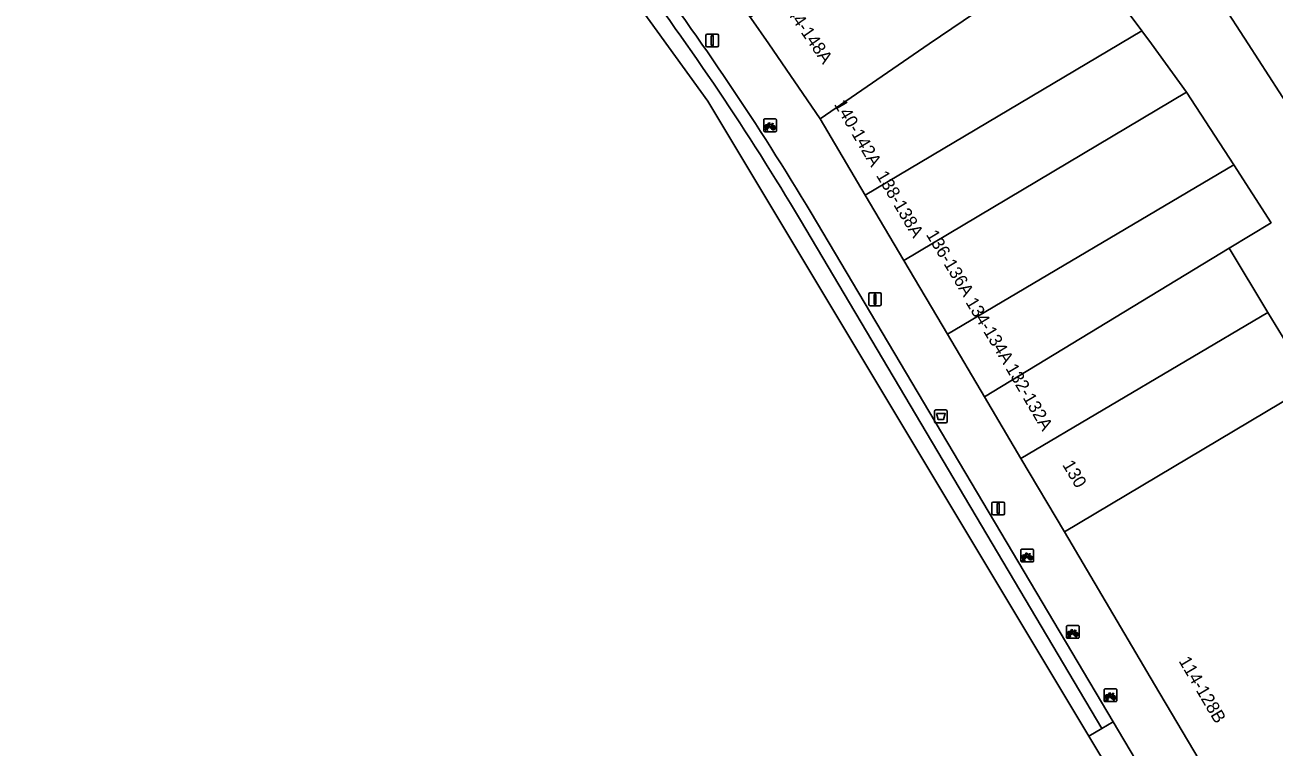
# Model space of a CAD drawing. Extents: x 160856 to 161310, y 384024 to 384878.
# Drawn here: x 160978.4 to 161076.4, y 384444.8 to 384501.5 of the extents above; entities that cross this region are included whole.
import ezdxf

# ---------------------------------------------------------------- set-up
doc = ezdxf.new("R2010")
doc.units = 0
for name, color, linetype in [('IMGEO_Afvalbak', 7, 'Continuous'), ('IMGEO_Fietsenrek', 7, 'Continuous'), ('IMGEO_Fietspad_gesloten', 7, 'Continuous'), ('IMGEO_Fietspad_open', 7, 'Continuous'), ('IMGEO_Lichtmast', 7, 'Continuous'), ('IMGEO_Pand', 7, 'Continuous'), ('IMGEO_Pand_nummerreeks', 7, 'Continuous'), ('IMGEO_Rijbaan_lokaal_open', 7, 'Continuous'), ('IMGEO_Voetpad_open', 7, 'Continuous')]:
    doc.layers.add(name, color=color, linetype=linetype)

msp = doc.modelspace()

# ---------------------------------------------------------------- linework, layer by layer
at = {"layer": 'IMGEO_Afvalbak'}
for p, q in [((161049.779, 384470.364), (161049.779, 384471.164)), ((161049.779, 384471.164), (161049.779, 384470.364)), ((161049.879, 384471.264), (161050.669, 384471.264)), ((161050.669, 384471.264), (161049.879, 384471.264)), ((161050.769, 384471.164), (161050.769, 384470.364)), ((161050.769, 384470.364), (161050.769, 384471.164)), ((161050.669, 384470.264), (161049.879, 384470.264)), ((161049.879, 384470.264), (161050.669, 384470.264))]:
    msp.add_line(p, q, dxfattribs=at)
msp.add_lwpolyline([(161049.922, 384470.978), (161050.626, 384470.978), (161050.477, 384470.508), (161050.071, 384470.508), (161049.922, 384470.978)], dxfattribs=at)
for centre, start, end in [((161049.879, 384471.164), 90, 180), ((161049.879, 384471.164), 90, 180), ((161050.669, 384471.164), 0, 90), ((161050.669, 384471.164), 360, 90), ((161049.879, 384470.364), 180, 270), ((161049.879, 384470.364), 180, 270), ((161050.669, 384470.364), 270, 0), ((161050.669, 384470.364), 270, 0)]:
    msp.add_arc(centre, 0.1, start, end, dxfattribs=at)
at = {"layer": 'IMGEO_Fietsenrek'}
for p, q in [((161036.368, 384493.185), (161036.368, 384494.026)), ((161036.368, 384494.026), (161036.368, 384493.185)), ((161036.443, 384494.11), (161037.284, 384494.11)), ((161037.284, 384494.11), (161036.443, 384494.11)), ((161037.055, 384493.659), (161037.091, 384493.564)), ((161037.368, 384494.035), (161037.368, 384493.194)), ((161037.368, 384493.194), (161037.368, 384494.035)), ((161037.293, 384493.11), (161036.452, 384493.11)), ((161036.452, 384493.11), (161037.293, 384493.11)), ((161036.495, 384493.194), (161036.534, 384493.354)), ((161036.529, 384493.194), (161036.495, 384493.194)), ((161036.564, 384493.342), (161036.529, 384493.194)), ((161036.606, 384493.366), (161036.605, 384493.37)), ((161036.647, 384493.194), (161036.613, 384493.336)), ((161036.637, 384493.377), (161036.638, 384493.37)), ((161036.645, 384493.34), (161036.68, 384493.194)), ((161036.68, 384493.194), (161036.647, 384493.194)), ((161056.556, 384459.416), (161056.556, 384460.257)), ((161056.556, 384460.257), (161056.556, 384459.416)), ((161056.631, 384460.341), (161057.472, 384460.341)), ((161057.472, 384460.341), (161056.631, 384460.341)), ((161057.556, 384460.266), (161057.556, 384459.425)), ((161057.556, 384459.425), (161057.556, 384460.266)), ((161057.481, 384459.341), (161056.64, 384459.341)), ((161056.64, 384459.341), (161057.481, 384459.341)), ((161056.683, 384459.425), (161056.722, 384459.585)), ((161056.717, 384459.425), (161056.683, 384459.425)), ((161056.752, 384459.573), (161056.717, 384459.425)), ((161056.794, 384459.597), (161056.793, 384459.601)), ((161056.835, 384459.425), (161056.801, 384459.567)), ((161056.825, 384459.608), (161056.826, 384459.601)), ((161056.833, 384459.571), (161056.868, 384459.425)), ((161056.868, 384459.425), (161056.835, 384459.425)), ((161057.243, 384459.89), (161057.279, 384459.795)), ((161060.212, 384454.337), (161061.053, 384454.337)), ((161061.053, 384454.337), (161060.212, 384454.337)), ((161060.137, 384453.412), (161060.137, 384454.253)), ((161060.137, 384454.253), (161060.137, 384453.412)), ((161060.264, 384453.421), (161060.303, 384453.581)), ((161060.298, 384453.421), (161060.264, 384453.421)), ((161060.333, 384453.569), (161060.298, 384453.421)), ((161060.375, 384453.593), (161060.374, 384453.597)), ((161060.416, 384453.421), (161060.382, 384453.563)), ((161060.406, 384453.604), (161060.407, 384453.597)), ((161060.414, 384453.567), (161060.449, 384453.421)), ((161060.449, 384453.421), (161060.416, 384453.421)), ((161060.824, 384453.886), (161060.86, 384453.791)), ((161061.137, 384454.262), (161061.137, 384453.421)), ((161061.137, 384453.421), (161061.137, 384454.262)), ((161061.062, 384453.337), (161060.221, 384453.337)), ((161060.221, 384453.337), (161061.062, 384453.337)), ((161063.094, 384448.442), (161063.094, 384449.283)), ((161063.094, 384449.283), (161063.094, 384448.442)), ((161063.169, 384449.367), (161064.01, 384449.367)), ((161064.01, 384449.367), (161063.169, 384449.367)), ((161063.221, 384448.451), (161063.26, 384448.611)), ((161063.255, 384448.451), (161063.221, 384448.451)), ((161063.29, 384448.599), (161063.255, 384448.451)), ((161063.332, 384448.623), (161063.331, 384448.627)), ((161063.373, 384448.451), (161063.339, 384448.593)), ((161063.363, 384448.634), (161063.364, 384448.627)), ((161063.371, 384448.597), (161063.406, 384448.451)), ((161063.406, 384448.451), (161063.373, 384448.451)), ((161063.781, 384448.916), (161063.817, 384448.821)), ((161064.094, 384449.292), (161064.094, 384448.451)), ((161064.094, 384448.451), (161064.094, 384449.292)), ((161064.019, 384448.367), (161063.178, 384448.367)), ((161063.178, 384448.367), (161064.019, 384448.367))]:
    msp.add_line(p, q, dxfattribs=at)
for points in [[(161036.702, 384493.584), (161036.65, 384493.494), (161036.61, 384493.469), (161036.611, 384493.516), (161036.666, 384493.61)], [(161036.681, 384493.636), (161036.776, 384493.8), (161036.862, 384493.786), (161036.864, 384493.777), (161036.808, 384493.766), (161036.781, 384493.721), (161037.037, 384493.68)], [(161036.977, 384493.392), (161036.927, 384493.392), (161036.736, 384493.643), (161036.717, 384493.611)], [(161037.024, 384493.655), (161036.767, 384493.696), (161036.75, 384493.667), (161036.917, 384493.447), (161037.024, 384493.655)], [(161037.072, 384493.557), (161037.042, 384493.634), (161036.933, 384493.416), (161036.976, 384493.416)], [(161037.037, 384493.68), (161037.062, 384493.729), (161037.056, 384493.733), (161037.033, 384493.737), (161037.021, 384493.744), (161037.02, 384493.747), (161037.022, 384493.752), (161037.117, 384493.737), (161037.119, 384493.727), (161037.109, 384493.714), (161037.097, 384493.708), (161037.083, 384493.714), (161037.055, 384493.659)], [(161037.006, 384493.416), (161037.126, 384493.415), (161037.082, 384493.529)], [(161037.102, 384493.536), (161037.157, 384493.391), (161037.007, 384493.391)], [(161056.89, 384459.815), (161056.838, 384459.725), (161056.798, 384459.7), (161056.799, 384459.747), (161056.854, 384459.841)], [(161056.869, 384459.867), (161056.964, 384460.031), (161057.05, 384460.017), (161057.052, 384460.008), (161056.996, 384459.997), (161056.969, 384459.952), (161057.225, 384459.911)], [(161057.165, 384459.623), (161057.115, 384459.623), (161056.924, 384459.874), (161056.905, 384459.842)], [(161057.212, 384459.886), (161056.955, 384459.927), (161056.938, 384459.898), (161057.105, 384459.678), (161057.212, 384459.886)], [(161057.26, 384459.788), (161057.23, 384459.865), (161057.121, 384459.647), (161057.164, 384459.647)], [(161057.194, 384459.647), (161057.314, 384459.646), (161057.27, 384459.76)], [(161057.29, 384459.767), (161057.345, 384459.622), (161057.195, 384459.622)], [(161057.225, 384459.911), (161057.25, 384459.96), (161057.244, 384459.964), (161057.221, 384459.968), (161057.209, 384459.975), (161057.208, 384459.978), (161057.21, 384459.983), (161057.305, 384459.968), (161057.307, 384459.958), (161057.297, 384459.945), (161057.285, 384459.939), (161057.271, 384459.945), (161057.243, 384459.89)], [(161060.471, 384453.811), (161060.419, 384453.721), (161060.379, 384453.696), (161060.38, 384453.743), (161060.435, 384453.837)], [(161060.45, 384453.863), (161060.545, 384454.027), (161060.631, 384454.013), (161060.633, 384454.004), (161060.577, 384453.993), (161060.55, 384453.948), (161060.806, 384453.907)], [(161060.746, 384453.619), (161060.696, 384453.619), (161060.505, 384453.87), (161060.486, 384453.838)], [(161060.793, 384453.882), (161060.536, 384453.923), (161060.519, 384453.894), (161060.686, 384453.674), (161060.793, 384453.882)], [(161060.841, 384453.784), (161060.811, 384453.861), (161060.702, 384453.643), (161060.745, 384453.643)], [(161060.775, 384453.643), (161060.895, 384453.642), (161060.851, 384453.756)], [(161060.871, 384453.763), (161060.926, 384453.618), (161060.776, 384453.618)], [(161060.806, 384453.907), (161060.831, 384453.956), (161060.825, 384453.96), (161060.802, 384453.964), (161060.79, 384453.971), (161060.789, 384453.974), (161060.791, 384453.979), (161060.886, 384453.964), (161060.888, 384453.954), (161060.878, 384453.941), (161060.866, 384453.935), (161060.852, 384453.941), (161060.824, 384453.886)], [(161063.428, 384448.841), (161063.376, 384448.751), (161063.336, 384448.726), (161063.337, 384448.773), (161063.392, 384448.867)], [(161063.407, 384448.893), (161063.502, 384449.057), (161063.588, 384449.043), (161063.59, 384449.034), (161063.534, 384449.023), (161063.507, 384448.978), (161063.763, 384448.937)], [(161063.703, 384448.649), (161063.653, 384448.649), (161063.462, 384448.9), (161063.443, 384448.868)], [(161063.75, 384448.912), (161063.493, 384448.953), (161063.476, 384448.924), (161063.643, 384448.704), (161063.75, 384448.912)], [(161063.798, 384448.814), (161063.768, 384448.891), (161063.659, 384448.673), (161063.702, 384448.673)], [(161063.732, 384448.673), (161063.852, 384448.672), (161063.808, 384448.786)], [(161063.828, 384448.793), (161063.883, 384448.648), (161063.733, 384448.648)], [(161063.763, 384448.937), (161063.788, 384448.986), (161063.782, 384448.99), (161063.759, 384448.994), (161063.747, 384449.001), (161063.746, 384449.004), (161063.748, 384449.009), (161063.843, 384448.994), (161063.845, 384448.984), (161063.835, 384448.971), (161063.823, 384448.965), (161063.809, 384448.971), (161063.781, 384448.916)]]:
    msp.add_lwpolyline(points, dxfattribs=at)
for centre, radius, start, end in [((161036.446, 384494.032), 0.0779, 92.4484, 184.28452), ((161036.446, 384494.032), 0.0779, 92.4484, 184.28452), ((161036.608, 384493.495), 0.159, 62.67661, 242.13685), ((161036.608, 384493.495), 0.129, 63.31916, 238.90302), ((161036.608, 384493.495), 0.129, 283.60429, 43.43025), ((161036.608, 384493.495), 0.159, 283.5766, 46.60424), ((161037.135, 384493.411), 0.159, 113.3408, 178.32165), ((161037.135, 384493.411), 0.159, 187.0065, 105.77075), ((161037.29, 384494.032), 0.0779, 2.4484, 94.28452), ((161037.29, 384494.032), 0.0779, 2.4484, 94.28452), ((161036.446, 384493.188), 0.0779, 182.4484, 274.28452), ((161036.446, 384493.188), 0.0779, 182.4484, 274.28452), ((161036.588, 384493.366), 0.0499, 12.8025, 158.69338), ((161036.608, 384493.495), 0.159, 253.99666, 271.78671), ((161036.588, 384493.366), 0.0174, 12.8025, 163.45023), ((161036.608, 384493.495), 0.129, 253.41502, 269.02044), ((161037.135, 384493.411), 0.129, 113.92302, 177.95563), ((161037.135, 384493.411), 0.129, 188.67146, 104.58832), ((161037.29, 384493.188), 0.0779, 272.4484, 4.28452), ((161037.29, 384493.188), 0.0779, 272.4484, 4.28452), ((161056.634, 384460.263), 0.0779, 92.4484, 184.28452), ((161056.634, 384460.263), 0.0779, 92.4484, 184.28452), ((161057.478, 384460.263), 0.0779, 2.4484, 94.28452), ((161057.478, 384460.263), 0.0779, 2.4484, 94.28452), ((161056.634, 384459.419), 0.0779, 182.4484, 274.28452), ((161056.634, 384459.419), 0.0779, 182.4484, 274.28452), ((161056.796, 384459.726), 0.159, 62.67661, 242.13685), ((161056.796, 384459.726), 0.129, 63.31916, 238.90302), ((161056.776, 384459.597), 0.0499, 12.8025, 158.69338), ((161056.796, 384459.726), 0.159, 253.99666, 271.78671), ((161056.776, 384459.597), 0.0174, 12.8025, 163.45023), ((161056.796, 384459.726), 0.129, 253.41502, 269.02044), ((161056.796, 384459.726), 0.129, 283.60429, 43.43025), ((161056.796, 384459.726), 0.159, 283.5766, 46.60424), ((161057.323, 384459.642), 0.159, 113.3408, 178.32165), ((161057.323, 384459.642), 0.159, 187.0065, 105.77075), ((161057.323, 384459.642), 0.129, 113.92302, 177.95563), ((161057.323, 384459.642), 0.129, 188.67146, 104.58832), ((161057.478, 384459.419), 0.0779, 272.4484, 4.28452), ((161057.478, 384459.419), 0.0779, 272.4484, 4.28452), ((161060.215, 384454.259), 0.0779, 92.4484, 184.28452), ((161060.215, 384454.259), 0.0779, 92.4484, 184.28452), ((161061.059, 384454.259), 0.0779, 2.4484, 94.28452), ((161061.059, 384454.259), 0.0779, 2.4484, 94.28452), ((161060.215, 384453.415), 0.0779, 182.4484, 274.28452), ((161060.215, 384453.415), 0.0779, 182.4484, 274.28452), ((161060.377, 384453.722), 0.159, 62.67661, 242.13685), ((161060.377, 384453.722), 0.129, 63.31916, 238.90302), ((161060.357, 384453.593), 0.0499, 12.8025, 158.69338), ((161060.377, 384453.722), 0.159, 253.99666, 271.78671), ((161060.357, 384453.593), 0.0174, 12.8025, 163.45023), ((161060.377, 384453.722), 0.129, 253.41502, 269.02044), ((161060.377, 384453.722), 0.129, 283.60429, 43.43025), ((161060.377, 384453.722), 0.159, 283.5766, 46.60424), ((161060.904, 384453.638), 0.159, 113.3408, 178.32165), ((161060.904, 384453.638), 0.159, 187.0065, 105.77075), ((161060.904, 384453.638), 0.129, 113.92302, 177.95563), ((161060.904, 384453.638), 0.129, 188.67146, 104.58832), ((161061.059, 384453.415), 0.0779, 272.4484, 4.28452), ((161061.059, 384453.415), 0.0779, 272.4484, 4.28452), ((161063.172, 384449.289), 0.0779, 92.4484, 184.28452), ((161063.172, 384449.289), 0.0779, 92.4484, 184.28452), ((161063.334, 384448.752), 0.159, 62.67661, 242.13685), ((161063.334, 384448.752), 0.129, 63.31916, 238.90302), ((161063.314, 384448.623), 0.0499, 12.8025, 158.69338), ((161063.334, 384448.752), 0.159, 253.99666, 271.78671), ((161063.314, 384448.623), 0.0174, 12.8025, 163.45023), ((161063.334, 384448.752), 0.129, 253.41502, 269.02044), ((161063.334, 384448.752), 0.129, 283.60429, 43.43025), ((161063.334, 384448.752), 0.159, 283.5766, 46.60424), ((161063.861, 384448.668), 0.159, 113.3408, 178.32165), ((161063.861, 384448.668), 0.159, 187.0065, 105.77075), ((161063.861, 384448.668), 0.129, 113.92302, 177.95563), ((161063.861, 384448.668), 0.129, 188.67146, 104.58832), ((161064.016, 384449.289), 0.0779, 2.4484, 94.28452), ((161064.016, 384449.289), 0.0779, 2.4484, 94.28452), ((161064.016, 384448.445), 0.0779, 272.4484, 4.28452), ((161064.016, 384448.445), 0.0779, 272.4484, 4.28452), ((161063.172, 384448.445), 0.0779, 182.4484, 274.28452), ((161063.172, 384448.445), 0.0779, 182.4484, 274.28452)]:
    msp.add_arc(centre, radius, start, end, dxfattribs=at)
at = {"layer": 'IMGEO_Fietspad_gesloten'}
for points in [[(161025.88, 384506.051), (161024.93, 384505.299), (161031.994, 384495.497), (161061.891, 384445.653)], [(161061.891, 384445.653), (161062.919, 384446.259), (161039.255, 384486.177)]]:
    msp.add_lwpolyline(points, dxfattribs=at)
msp.add_arc((160849.822, 384373.128), 220.601, 30.82769, 37.05261, dxfattribs=at)
at = {"layer": 'IMGEO_Fietspad_open'}
msp.add_lwpolyline([(161039.255, 384486.177), (161062.919, 384446.259), (161063.799, 384446.778), (161040.086, 384486.747)], dxfattribs=at)
msp.add_lwpolyline([(161063.662, 384442.699), (161064.671, 384443.305), (161065.547, 384443.832), (161063.799, 384446.778), (161062.919, 384446.259), (161061.891, 384445.653)], close=True, dxfattribs=at)
for centre, radius, start, end in [((160846.585, 384370.955), 225.5, 30.89645, 37.00358), ((160849.822, 384373.128), 220.601, 30.82769, 37.05261)]:
    msp.add_arc(centre, radius, start, end, dxfattribs=at)
at = {"layer": 'IMGEO_Lichtmast'}
for p, q in [((161031.837, 384499.868), (161031.837, 384500.668)), ((161031.837, 384500.668), (161031.837, 384499.868)), ((161031.937, 384500.768), (161032.727, 384500.768)), ((161032.727, 384500.768), (161031.937, 384500.768)), ((161032.827, 384500.668), (161032.827, 384499.868)), ((161032.827, 384499.868), (161032.827, 384500.668)), ((161032.727, 384499.768), (161031.937, 384499.768)), ((161031.937, 384499.768), (161032.727, 384499.768)), ((161044.611, 384479.55), (161044.611, 384480.35)), ((161044.611, 384480.35), (161044.611, 384479.55)), ((161044.711, 384480.45), (161045.501, 384480.45)), ((161045.501, 384480.45), (161044.711, 384480.45)), ((161045.601, 384480.35), (161045.601, 384479.55)), ((161045.601, 384479.55), (161045.601, 384480.35)), ((161045.501, 384479.45), (161044.711, 384479.45)), ((161044.711, 384479.45), (161045.501, 384479.45)), ((161054.287, 384463.135), (161054.287, 384463.935)), ((161054.287, 384463.935), (161054.287, 384463.135)), ((161054.387, 384464.035), (161055.177, 384464.035)), ((161055.177, 384464.035), (161054.387, 384464.035)), ((161055.277, 384463.935), (161055.277, 384463.135)), ((161055.277, 384463.135), (161055.277, 384463.935)), ((161055.177, 384463.035), (161054.387, 384463.035)), ((161054.387, 384463.035), (161055.177, 384463.035))]:
    msp.add_line(p, q, dxfattribs=at)
for points in [[(161032.257, 384500.643), (161032.407, 384500.643), (161032.407, 384499.893), (161032.257, 384499.893), (161032.257, 384500.643)], [(161045.031, 384480.325), (161045.181, 384480.325), (161045.181, 384479.575), (161045.031, 384479.575), (161045.031, 384480.325)], [(161054.707, 384463.91), (161054.857, 384463.91), (161054.857, 384463.16), (161054.707, 384463.16), (161054.707, 384463.91)]]:
    msp.add_lwpolyline(points, dxfattribs=at)
for centre, start, end in [((161031.937, 384500.668), 90, 180), ((161031.937, 384500.668), 90, 180), ((161032.727, 384500.668), 0, 90), ((161032.727, 384500.668), 360, 90), ((161031.937, 384499.868), 180, 270), ((161031.937, 384499.868), 180, 270), ((161032.727, 384499.868), 270, 0), ((161032.727, 384499.868), 270, 0), ((161044.711, 384480.35), 90, 180), ((161044.711, 384480.35), 90, 180), ((161045.501, 384480.35), 0, 90), ((161045.501, 384480.35), 360, 90), ((161044.711, 384479.55), 180, 270), ((161044.711, 384479.55), 180, 270), ((161045.501, 384479.55), 270, 0), ((161045.501, 384479.55), 270, 0), ((161054.387, 384463.935), 90, 180), ((161054.387, 384463.935), 90, 180), ((161055.177, 384463.935), 0, 90), ((161055.177, 384463.935), 360, 90), ((161054.387, 384463.135), 180, 270), ((161054.387, 384463.135), 180, 270), ((161055.177, 384463.135), 270, 0), ((161055.177, 384463.135), 270, 0)]:
    msp.add_arc(centre, 0.1, start, end, dxfattribs=at)
at = {"layer": 'IMGEO_Pand'}
for points in [[(161040.804, 384494.109), (161049.367, 384500), (161060.762, 384507.759), (161060.912, 384507.86), (161055.172, 384515.721), (161035.318, 384502.112), (161035.397, 384501.998), (161036.766, 384500)], [(161086.528, 384500), (161078.403, 384512.582), (161069.859, 384507.042), (161070.066, 384506.722), (161074.406, 384500), (161086.57, 384481.163), (161095.125, 384486.687), (161089.266, 384495.761)], [(161066.061, 384501.015), (161062.467, 384505.869), (161062.285, 384505.641), (161060.762, 384507.759), (161049.367, 384500), (161040.804, 384494.109), (161044.336, 384488.136)], [(161069.571, 384496.22), (161066.804, 384500), (161066.061, 384501.015), (161044.336, 384488.136), (161047.368, 384483.008)], [(161069.571, 384496.22), (161047.368, 384483.008), (161050.789, 384477.224), (161073.262, 384490.514)], [(161072.904, 384483.963), (161076.199, 384485.966), (161073.262, 384490.514), (161050.789, 384477.224), (161053.697, 384472.306)], [(161072.904, 384483.963), (161053.697, 384472.306), (161056.563, 384467.459), (161075.954, 384478.925)], [(161079.386, 384473.255), (161075.954, 384478.925), (161056.563, 384467.459), (161059.97, 384461.697)], [(161079.386, 384473.255), (161059.97, 384461.697), (161067.054, 384449.718), (161074.052, 384437.883), (161077.552, 384431.965), (161085.69, 384435.488), (161085.88, 384434.994), (161095.394, 384438.657), (161094.42, 384441.188), (161097.341, 384442.312), (161094.568, 384450.014), (161094.201, 384451.035), (161087.735, 384461.947), (161080.492, 384474.172)]]:
    msp.add_lwpolyline(points, close=True, dxfattribs=at)
at = {"layer": 'IMGEO_Rijbaan_lokaal_open'}
for points in [[(161086.57, 384481.163), (161074.406, 384500), (161070.066, 384506.722), (161069.859, 384507.042), (161069.287, 384506.671), (161064.523, 384513.188), (161061.847, 384516.849), (161050.778, 384531.991), (161024.428, 384568.037)], [(161021.221, 384561.973), (161025.146, 384556.687), (161029.946, 384550.221), (161029.569, 384549.908), (161034.956, 384543.407), (161038.456, 384538.613), (161041.965, 384533.808), (161045.474, 384529.002), (161048.983, 384524.197), (161055.172, 384515.721), (161060.912, 384507.86), (161060.762, 384507.759), (161062.285, 384505.641), (161062.467, 384505.869), (161066.061, 384501.015), (161066.804, 384500), (161069.571, 384496.22), (161073.262, 384490.514), (161076.199, 384485.966), (161072.904, 384483.963), (161075.954, 384478.925), (161079.386, 384473.255)]]:
    msp.add_lwpolyline(points, dxfattribs=at)
at = {"layer": 'IMGEO_Voetpad_open'}
for points in [[(161036.766, 384500), (161035.397, 384501.998), (161035.318, 384502.112), (161030.638, 384508.94), (161031.821, 384509.921), (161028.032, 384514.494), (161024.243, 384519.066), (161020.454, 384523.638), (161016.665, 384528.211), (161011.287, 384534.701), (161006.157, 384540.892), (161004.916, 384539.863), (161000.723, 384544.923), (161000, 384545.796), (160993.672, 384553.434), (160989.204, 384558.838), (160989.072, 384558.729), (160985.147, 384563.476), (160983.078, 384565.978), (160981.931, 384567.366), (160982.264, 384571.633), (160981.645, 384572.376), (160979.156, 384575.363), (160978.381, 384574.954)], [(161082.898, 384415.232), (161087.871, 384407.534), (161089.488, 384412.11), (161087.978, 384417.265), (161083.529, 384422.548), (161081.445, 384423.321), (161077.145, 384431.612), (161077.552, 384431.965), (161074.052, 384437.883), (161067.054, 384449.718), (161059.97, 384461.697), (161056.563, 384467.459), (161053.697, 384472.306), (161050.789, 384477.224), (161047.368, 384483.008), (161044.336, 384488.136), (161040.804, 384494.109), (161036.766, 384500)], [(161040.086, 384486.747), (161063.799, 384446.778), (161065.547, 384443.832), (161066.518, 384442.195), (161071.087, 384434.493)]]:
    msp.add_lwpolyline(points, dxfattribs=at)
msp.add_arc((160846.585, 384370.955), 225.5, 30.89645, 37.00358, dxfattribs=at)

# ---------------------------------------------------------------- texts
at = {"layer": 'IMGEO_Pand_nummerreeks'}
for s, rotation, p in [('144-148A', 304.73169, (161037.726, 384503.109)), ('140-142A', 300.59574, (161041.869, 384495.256)), ('138-138A', 300.59574, (161045.167, 384489.678)), ('136-136A', 301.10881, (161049.084, 384485.034)), ('134-134A', 301.38319, (161052.186, 384479.718)), ('132-132A', 300.44527, (161055.325, 384474.538)), ('130', 300.59764, (161059.783, 384466.965)), ('114-128B', 300.53585, (161068.913, 384451.563))]:
    msp.add_text(s, height=1, rotation=rotation, dxfattribs=at).set_placement(p)

doc.saveas('drawing.dxf')
